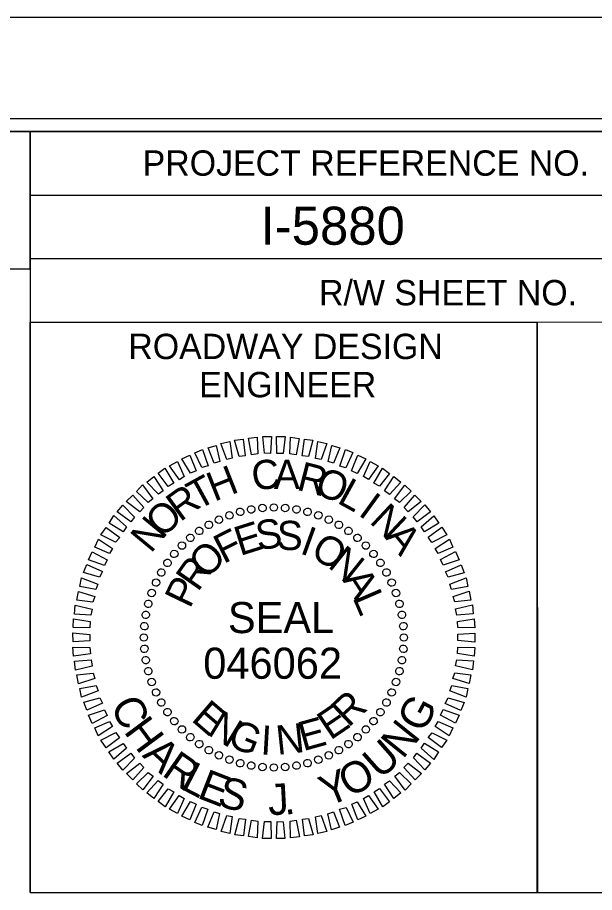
# Model space of a CAD drawing. Extents: x 1640342 to 1730599, y 538663 to 843747.
# Drawn here: x 1730133.49 to 1730156.25, y 539096.41 to 539130.92 of the extents above; entities that cross this region are included whole.
import ezdxf

# ---------------------------------------------------------------- set-up
doc = ezdxf.new("R2010")
doc.units = 0
for name, color, linetype in [('Default', 7, 'Continuous'), ('Old_Level_2', 7, 'Continuous'), ('Prop Dimension Text', 7, 'Continuous'), ('Sheet Data Field CELL', 7, 'Continuous'), ('Sheet Plan CELL', 7, 'Continuous'), ('Sheet Plan Layout CELL', 7, 'Continuous'), ('Sheet Plot Border Inside CELL', 7, 'Continuous'), ('Sheet Plot Border Outside CELL', 7, 'Continuous')]:
    doc.layers.add(name, color=color, linetype=linetype)

msp = doc.modelspace()

# ---------------------------------------------------------------- linework, layer by layer
at = {"layer": 'Old_Level_2'}
for p, q in [((1730142.266, 539111.422), (1730142.266, 539111.422)), ((1730142.715, 539111.512), (1730142.715, 539111.512)), ((1730143.153, 539111.581), (1730143.153, 539111.581)), ((1730143.603, 539111.599), (1730143.603, 539111.599)), ((1730144.053, 539111.576), (1730144.053, 539111.576)), ((1730144.494, 539111.512), (1730144.494, 539111.512)), ((1730144.925, 539111.428), (1730144.925, 539111.428)), ((1730141.433, 539111.121), (1730141.433, 539111.121)), ((1730141.839, 539111.292), (1730141.839, 539111.292)), ((1730145.357, 539111.292), (1730145.357, 539111.292)), ((1730145.769, 539111.115), (1730145.769, 539111.115)), ((1730140.654, 539110.668), (1730140.654, 539110.668)), ((1730141.038, 539110.91), (1730141.038, 539110.91)), ((1730146.171, 539110.918), (1730146.171, 539110.918)), ((1730146.543, 539110.669), (1730146.543, 539110.669)), ((1730140.3, 539110.406), (1730140.3, 539110.406)), ((1730146.906, 539110.399), (1730146.906, 539110.399)), ((1730139.968, 539110.094), (1730139.968, 539110.094)), ((1730147.228, 539110.098), (1730147.228, 539110.098)), ((1730139.667, 539109.771), (1730139.667, 539109.771)), ((1730147.541, 539109.766), (1730147.541, 539109.766)), ((1730139.398, 539109.409), (1730139.398, 539109.409)), ((1730147.803, 539109.412), (1730147.803, 539109.412)), ((1730139.148, 539109.036), (1730139.148, 539109.036)), ((1730148.045, 539109.028), (1730148.045, 539109.028)), ((1730138.951, 539108.634), (1730138.951, 539108.634)), ((1730148.256, 539108.633), (1730148.256, 539108.633)), ((1730138.774, 539108.222), (1730138.774, 539108.222)), ((1730148.427, 539108.227), (1730148.427, 539108.227)), ((1730138.638, 539107.79), (1730138.638, 539107.79)), ((1730148.557, 539107.8), (1730148.557, 539107.8)), ((1730138.554, 539107.359), (1730138.554, 539107.359)), ((1730148.646, 539107.351), (1730148.646, 539107.351)), ((1730138.49, 539106.919), (1730138.49, 539106.919)), ((1730148.715, 539106.913), (1730148.715, 539106.913)), ((1730138.467, 539106.468), (1730138.467, 539106.468)), ((1730143.6, 539106.466), (1730143.6, 539106.466)), ((1730148.733, 539106.463), (1730148.733, 539106.463)), ((1730138.485, 539106.019), (1730138.485, 539106.019)), ((1730148.711, 539106.013), (1730148.711, 539106.013)), ((1730138.554, 539105.58), (1730138.554, 539105.58)), ((1730148.647, 539105.572), (1730148.647, 539105.572)), ((1730138.644, 539105.132), (1730138.644, 539105.132)), ((1730148.562, 539105.141), (1730148.562, 539105.141)), ((1730138.774, 539104.705), (1730138.774, 539104.705)), ((1730148.427, 539104.709), (1730148.427, 539104.709)), ((1730138.945, 539104.299), (1730138.945, 539104.299)), ((1730148.25, 539104.297), (1730148.25, 539104.297)), ((1730139.156, 539103.903), (1730139.156, 539103.903)), ((1730148.052, 539103.895), (1730148.052, 539103.895)), ((1730139.398, 539103.519), (1730139.398, 539103.519)), ((1730147.803, 539103.523), (1730147.803, 539103.523)), ((1730139.66, 539103.166), (1730139.66, 539103.166)), ((1730147.533, 539103.16), (1730147.533, 539103.16)), ((1730139.972, 539102.834), (1730139.972, 539102.834)), ((1730147.232, 539102.838), (1730147.232, 539102.838)), ((1730140.295, 539102.533), (1730140.295, 539102.533)), ((1730146.9, 539102.525), (1730146.9, 539102.525)), ((1730140.657, 539102.263), (1730140.657, 539102.263)), ((1730141.03, 539102.014), (1730141.03, 539102.014)), ((1730146.163, 539102.022), (1730146.163, 539102.022)), ((1730146.547, 539102.264), (1730146.547, 539102.264)), ((1730141.432, 539101.816), (1730141.432, 539101.816)), ((1730141.844, 539101.64), (1730141.844, 539101.64)), ((1730145.362, 539101.64), (1730145.362, 539101.64)), ((1730145.768, 539101.81), (1730145.768, 539101.81)), ((1730142.276, 539101.504), (1730142.276, 539101.504)), ((1730142.707, 539101.419), (1730142.707, 539101.419)), ((1730143.148, 539101.355), (1730143.148, 539101.355)), ((1730143.598, 539101.333), (1730143.598, 539101.333)), ((1730144.048, 539101.351), (1730144.048, 539101.351)), ((1730144.486, 539101.42), (1730144.486, 539101.42)), ((1730144.934, 539101.509), (1730144.934, 539101.509))]:
    msp.add_line(p, q, dxfattribs=at)
for points in [[(1730141.74, 539113.479), (1730141.514, 539114.119), (1730141.86, 539114.196), (1730141.953, 539113.533)], [(1730142.228, 539113.6), (1730142.053, 539114.251), (1730142.39, 539114.287), (1730142.473, 539113.634)], [(1730142.718, 539113.669), (1730142.594, 539114.322), (1730142.941, 539114.369), (1730142.963, 539113.704)], [(1730143.228, 539113.729), (1730143.165, 539114.393), (1730143.503, 539114.389), (1730143.474, 539113.724)], [(1730143.719, 539113.728), (1730143.707, 539114.392), (1730144.045, 539114.388), (1730143.965, 539113.722)], [(1730144.231, 539113.706), (1730144.26, 539114.371), (1730144.598, 539114.316), (1730144.477, 539113.669)], [(1730144.723, 539113.633), (1730144.803, 539114.289), (1730145.142, 539114.243), (1730144.969, 539113.606)], [(1730145.246, 539113.53), (1730145.337, 539114.196), (1730145.686, 539114.12), (1730145.462, 539113.482)], [(1730140.753, 539113.165), (1730140.477, 539113.753), (1730140.782, 539113.881), (1730141.008, 539113.231)], [(1730141.251, 539113.337), (1730141.005, 539113.946), (1730141.321, 539114.044), (1730141.465, 539113.412)], [(1730145.739, 539113.405), (1730145.881, 539114.042), (1730146.2, 539113.945), (1730145.955, 539113.337)], [(1730146.202, 539113.229), (1730146.426, 539113.877), (1730146.714, 539113.76), (1730146.439, 539113.162)], [(1730139.872, 539112.689), (1730139.484, 539113.235), (1730139.798, 539113.404), (1730140.064, 539112.815)], [(1730140.307, 539112.942), (1730139.97, 539113.509), (1730140.285, 539113.658), (1730140.531, 539113.038)], [(1730146.666, 539113.043), (1730146.911, 539113.651), (1730147.23, 539113.513), (1730146.892, 539112.934)], [(1730147.14, 539112.816), (1730147.406, 539113.404), (1730147.715, 539113.235), (1730147.336, 539112.697)], [(1730139.427, 539112.426), (1730139.039, 539112.941), (1730139.302, 539113.139), (1730139.649, 539112.552)], [(1730147.543, 539112.547), (1730147.891, 539113.146), (1730148.16, 539112.936), (1730147.77, 539112.428)], [(1730139.044, 539112.112), (1730138.595, 539112.595), (1730138.868, 539112.815), (1730139.235, 539112.249)], [(1730147.968, 539112.248), (1730148.336, 539112.817), (1730148.606, 539112.596), (1730148.165, 539112.108)], [(1730138.64, 539111.788), (1730138.183, 539112.23), (1730138.424, 539112.48), (1730138.832, 539111.935)], [(1730148.362, 539111.938), (1730148.772, 539112.476), (1730149.021, 539112.235), (1730148.559, 539111.788)], [(1730138.309, 539111.425), (1730137.78, 539111.835), (1730138.032, 539112.074), (1730138.47, 539111.591)], [(1730148.736, 539111.586), (1730149.167, 539112.074), (1730149.417, 539111.833), (1730148.892, 539111.425)], [(1730137.958, 539111.03), (1730137.42, 539111.419), (1730137.64, 539111.689), (1730138.098, 539111.217)], [(1730149.1, 539111.225), (1730149.562, 539111.693), (1730149.782, 539111.42), (1730149.247, 539111.023)], [(1730137.658, 539110.636), (1730137.1, 539110.974), (1730137.289, 539111.274), (1730137.788, 539110.833)], [(1730149.414, 539110.831), (1730149.907, 539111.269), (1730150.107, 539110.976), (1730149.54, 539110.639)], [(1730137.359, 539110.222), (1730136.781, 539110.519), (1730136.98, 539110.808), (1730137.519, 539110.409)], [(1730149.687, 539110.417), (1730150.222, 539110.815), (1730150.422, 539110.511), (1730149.834, 539110.215)], [(1730137.121, 539109.778), (1730136.534, 539110.024), (1730136.682, 539110.343), (1730137.24, 539109.975)], [(1730149.961, 539109.972), (1730150.527, 539110.339), (1730150.665, 539110.025), (1730150.087, 539109.78)], [(1730136.925, 539109.304), (1730136.287, 539109.528), (1730136.435, 539109.848), (1730137.023, 539109.531)], [(1730150.173, 539109.536), (1730150.77, 539109.853), (1730150.909, 539109.528), (1730150.279, 539109.313)], [(1730136.728, 539108.851), (1730136.091, 539109.024), (1730136.219, 539109.343), (1730136.837, 539109.068)], [(1730150.365, 539109.058), (1730150.984, 539109.335), (1730151.102, 539109.02), (1730150.471, 539108.846)], [(1730136.583, 539108.358), (1730135.947, 539108.48), (1730136.013, 539108.818), (1730136.662, 539108.574)], [(1730150.537, 539108.571), (1730151.187, 539108.817), (1730151.255, 539108.481), (1730150.613, 539108.357)], [(1730136.459, 539107.865), (1730135.824, 539107.935), (1730135.889, 539108.284), (1730136.537, 539108.081)], [(1730150.668, 539108.082), (1730151.309, 539108.288), (1730151.376, 539107.941), (1730150.734, 539107.868)], [(1730136.386, 539107.342), (1730135.731, 539107.392), (1730135.766, 539107.74), (1730136.433, 539107.588)], [(1730150.769, 539107.593), (1730151.431, 539107.748), (1730151.468, 539107.401), (1730150.814, 539107.348)], [(1730136.344, 539106.85), (1730135.679, 539106.859), (1730135.694, 539107.197), (1730136.36, 539107.096)], [(1730150.839, 539107.103), (1730151.502, 539107.197), (1730151.528, 539106.85), (1730150.864, 539106.858)], [(1730136.343, 539106.339), (1730135.679, 539106.297), (1730135.673, 539106.644), (1730136.338, 539106.584)], [(1730150.858, 539106.592), (1730151.522, 539106.635), (1730151.528, 539106.287), (1730150.862, 539106.347)], [(1730136.362, 539105.828), (1730135.699, 539105.735), (1730135.672, 539106.082), (1730136.337, 539106.073)], [(1730150.857, 539106.081), (1730151.522, 539106.072), (1730151.507, 539105.735), (1730150.841, 539105.836)], [(1730136.432, 539105.339), (1730135.77, 539105.184), (1730135.733, 539105.531), (1730136.387, 539105.583)], [(1730150.814, 539105.59), (1730151.47, 539105.54), (1730151.435, 539105.191), (1730150.767, 539105.343)], [(1730136.532, 539104.85), (1730135.892, 539104.644), (1730135.824, 539104.991), (1730136.467, 539105.063)], [(1730150.742, 539105.067), (1730151.377, 539104.996), (1730151.311, 539104.647), (1730150.664, 539104.851)], [(1730136.663, 539104.361), (1730136.013, 539104.114), (1730135.946, 539104.451), (1730136.588, 539104.574)], [(1730150.617, 539104.574), (1730151.253, 539104.452), (1730151.188, 539104.114), (1730150.539, 539104.358)], [(1730136.836, 539103.873), (1730136.217, 539103.597), (1730136.099, 539103.911), (1730136.73, 539104.086)], [(1730150.472, 539104.081), (1730151.109, 539103.908), (1730150.982, 539103.588), (1730150.364, 539103.864)], [(1730137.028, 539103.396), (1730136.43, 539103.079), (1730136.292, 539103.404), (1730136.922, 539103.619)], [(1730150.276, 539103.627), (1730150.914, 539103.403), (1730150.766, 539103.084), (1730150.178, 539103.401)], [(1730137.24, 539102.96), (1730136.674, 539102.592), (1730136.535, 539102.907), (1730137.114, 539103.152)], [(1730150.08, 539103.153), (1730150.667, 539102.908), (1730150.519, 539102.588), (1730149.96, 539102.957)], [(1730137.514, 539102.515), (1730136.979, 539102.117), (1730136.779, 539102.42), (1730137.367, 539102.717)], [(1730149.842, 539102.71), (1730150.42, 539102.413), (1730150.22, 539102.123), (1730149.682, 539102.523)], [(1730137.787, 539102.1), (1730137.293, 539101.662), (1730137.094, 539101.955), (1730137.661, 539102.292)], [(1730149.542, 539102.295), (1730150.101, 539101.957), (1730149.911, 539101.658), (1730149.413, 539102.099)], [(1730138.1, 539101.707), (1730137.638, 539101.239), (1730137.419, 539101.511), (1730137.954, 539101.909)], [(1730149.243, 539101.902), (1730149.781, 539101.512), (1730149.561, 539101.242), (1730149.103, 539101.715)], [(1730138.465, 539101.345), (1730138.033, 539100.857), (1730137.784, 539101.098), (1730138.308, 539101.506)], [(1730148.892, 539101.507), (1730149.42, 539101.097), (1730149.169, 539100.857), (1730148.731, 539101.34)], [(1730138.839, 539100.994), (1730138.429, 539100.455), (1730138.179, 539100.696), (1730138.642, 539101.144)], [(1730148.56, 539101.143), (1730149.018, 539100.701), (1730148.777, 539100.452), (1730148.369, 539100.997)], [(1730139.233, 539100.684), (1730138.864, 539100.115), (1730138.595, 539100.335), (1730139.036, 539100.824)], [(1730148.157, 539100.819), (1730148.605, 539100.336), (1730148.333, 539100.117), (1730147.965, 539100.683)], [(1730139.657, 539100.385), (1730139.31, 539099.785), (1730139.04, 539099.995), (1730139.43, 539100.503)], [(1730147.774, 539100.506), (1730148.161, 539099.991), (1730147.899, 539099.792), (1730147.551, 539100.379)], [(1730140.061, 539100.115), (1730139.795, 539099.528), (1730139.485, 539099.696), (1730139.864, 539100.235)], [(1730140.535, 539099.889), (1730140.29, 539099.281), (1730139.971, 539099.419), (1730140.308, 539099.997)], [(1730146.893, 539099.989), (1730147.231, 539099.423), (1730146.916, 539099.274), (1730146.67, 539099.893)], [(1730147.329, 539100.242), (1730147.717, 539099.697), (1730147.403, 539099.528), (1730147.137, 539100.116)], [(1730140.998, 539099.702), (1730140.775, 539099.054), (1730140.486, 539099.172), (1730140.762, 539099.77)], [(1730141.462, 539099.526), (1730141.319, 539098.89), (1730141.001, 539098.987), (1730141.246, 539099.594)], [(1730145.949, 539099.595), (1730146.195, 539098.985), (1730145.88, 539098.888), (1730145.736, 539099.519)], [(1730146.447, 539099.767), (1730146.724, 539099.179), (1730146.419, 539099.051), (1730146.193, 539099.701)], [(1730141.955, 539099.402), (1730141.864, 539098.736), (1730141.515, 539098.812), (1730141.739, 539099.449)], [(1730142.478, 539099.299), (1730142.397, 539098.643), (1730142.059, 539098.688), (1730142.232, 539099.325)], [(1730142.97, 539099.226), (1730142.941, 539098.56), (1730142.602, 539098.616), (1730142.724, 539099.262)], [(1730144.483, 539099.262), (1730144.607, 539098.61), (1730144.26, 539098.563), (1730144.238, 539099.227)], [(1730144.972, 539099.332), (1730145.147, 539098.681), (1730144.811, 539098.644), (1730144.728, 539099.297)], [(1730145.461, 539099.453), (1730145.687, 539098.813), (1730145.341, 539098.735), (1730145.247, 539099.398)], [(1730143.482, 539099.204), (1730143.493, 539098.539), (1730143.156, 539098.544), (1730143.236, 539099.21)], [(1730143.973, 539099.202), (1730144.035, 539098.539), (1730143.698, 539098.543), (1730143.727, 539099.208)]]:
    msp.add_lwpolyline(points, close=True, dxfattribs=at)
for centre, major_axis in [((1730142.71, 539111.516), (-0.026, 0.145)), ((1730143.153, 539111.574), (-0.013, 0.147)), ((1730143.6, 539111.594), (0, 0.147)), ((1730144.047, 539111.574), (0.013, 0.147)), ((1730144.491, 539111.516), (0.026, 0.145)), ((1730141.846, 539111.285), (-0.05, 0.138)), ((1730142.273, 539111.419), (-0.038, 0.142)), ((1730144.928, 539111.419), (0.038, 0.142)), ((1730145.354, 539111.285), (0.05, 0.138)), ((1730141.036, 539110.907), (-0.074, 0.127)), ((1730141.433, 539111.114), (-0.062, 0.133)), ((1730145.768, 539111.114), (0.062, 0.133)), ((1730146.164, 539110.907), (0.074, 0.127)), ((1730140.659, 539110.667), (-0.084, 0.121)), ((1730146.542, 539110.667), (0.084, 0.121)), ((1730140.304, 539110.394), (-0.095, 0.113)), ((1730146.897, 539110.394), (0.095, 0.113)), ((1730139.672, 539109.762), (-0.113, 0.095)), ((1730139.974, 539110.092), (-0.104, 0.104)), ((1730147.227, 539110.092), (0.104, 0.104)), ((1730147.529, 539109.762), (0.113, 0.095)), ((1730139.4, 539109.407), (-0.121, 0.084)), ((1730147.801, 539109.407), (0.121, 0.084)), ((1730139.159, 539109.03), (-0.127, 0.074)), ((1730148.042, 539109.03), (0.127, 0.074)), ((1730138.953, 539108.633), (-0.133, 0.062)), ((1730148.248, 539108.633), (0.133, 0.062)), ((1730138.781, 539108.22), (-0.138, 0.05)), ((1730148.419, 539108.22), (0.138, 0.05)), ((1730138.647, 539107.793), (-0.142, 0.038)), ((1730148.554, 539107.793), (0.142, 0.038)), ((1730138.55, 539107.356), (-0.145, 0.026)), ((1730148.651, 539107.356), (0.145, 0.026)), ((1730138.492, 539106.913), (-0.147, 0.013)), ((1730148.709, 539106.913), (0.147, 0.013)), ((1730138.472, 539106.466), (-0.147, 0)), ((1730148.729, 539106.466), (0.147, 0)), ((1730138.492, 539106.019), (-0.147, -0.013)), ((1730148.709, 539106.019), (0.147, -0.013)), ((1730138.55, 539105.575), (-0.145, -0.026)), ((1730148.651, 539105.575), (0.145, -0.026)), ((1730138.647, 539105.139), (-0.142, -0.038)), ((1730148.554, 539105.139), (0.142, -0.038)), ((1730138.781, 539104.712), (-0.138, -0.05)), ((1730148.419, 539104.712), (0.138, -0.05)), ((1730138.953, 539104.299), (-0.133, -0.062)), ((1730148.248, 539104.299), (0.133, -0.062)), ((1730139.159, 539103.902), (-0.127, -0.074)), ((1730148.042, 539103.902), (0.127, -0.074)), ((1730139.4, 539103.524), (-0.121, -0.084)), ((1730147.801, 539103.524), (0.121, -0.084)), ((1730139.672, 539103.169), (-0.113, -0.095)), ((1730147.529, 539103.169), (0.113, -0.095)), ((1730139.974, 539102.84), (-0.104, -0.104)), ((1730140.304, 539102.537), (-0.095, -0.113)), ((1730146.897, 539102.537), (0.095, -0.113)), ((1730147.227, 539102.84), (0.104, -0.104)), ((1730140.659, 539102.265), (-0.084, -0.121)), ((1730146.542, 539102.265), (0.084, -0.121)), ((1730141.036, 539102.025), (-0.074, -0.127)), ((1730141.433, 539101.818), (-0.062, -0.133)), ((1730145.768, 539101.818), (0.062, -0.133)), ((1730146.164, 539102.025), (0.074, -0.127)), ((1730141.846, 539101.647), (-0.05, -0.138)), ((1730142.273, 539101.512), (-0.038, -0.142)), ((1730144.928, 539101.512), (0.038, -0.142)), ((1730145.354, 539101.647), (0.05, -0.138)), ((1730142.71, 539101.416), (-0.026, -0.145)), ((1730143.153, 539101.357), (-0.013, -0.147)), ((1730143.6, 539101.338), (0, -0.147)), ((1730144.047, 539101.357), (0.013, -0.147)), ((1730144.491, 539101.416), (0.026, -0.145))]:
    msp.add_ellipse(centre, major_axis=major_axis, ratio=0.999708, dxfattribs=at)
at = {"layer": 'Prop Dimension Text'}
msp.add_lwpolyline([(1730104.001, 539121.01), (1730133.983, 539121.01), (1730133.983, 539126.42), (1730104.001, 539126.42)], close=True, dxfattribs=at)
at = {"layer": 'Sheet Plan CELL'}
for p, q in [((1730133.98, 539123.91), (1730173.99, 539123.908)), ((1730133.983, 539121.403), (1730173.99, 539121.408)), ((1730133.983, 539121.403), (1730173.99, 539121.408)), ((1730133.983, 539121.403), (1730133.983, 539118.905)), ((1730153.993, 539118.905), (1730153.995, 539096.413))]:
    msp.add_line(p, q, dxfattribs=at)
for points in [[(1729873.99, 538916.418), (1729873.985, 539126.413), (1730133.983, 539126.42), (1730133.985, 539096.408), (1730173.993, 539096.405), (1730173.993, 538916.418)], [(1730173.998, 539126.418), (1729873.99, 539126.418), (1729873.99, 538916.418), (1730173.993, 538916.418)], [(1730133.983, 539126.42), (1730173.998, 539126.418), (1730173.99, 539121.408), (1730133.983, 539121.403)], [(1730133.983, 539118.905), (1730153.993, 539118.905), (1730153.993, 539096.403), (1730133.985, 539096.408)], [(1730153.993, 539118.905), (1730173.99, 539118.908), (1730173.993, 539096.405), (1730153.993, 539096.403)]]:
    msp.add_lwpolyline(points, close=True, dxfattribs=at)
at = {"layer": 'Sheet Plan Layout CELL'}
msp.add_lwpolyline([(1730126.14, 539084.12), (1730173.995, 539084.12), (1730174, 539126.418), (1730126.14, 539126.418)], close=True, dxfattribs=at)
at = {"layer": 'Sheet Plot Border Inside CELL'}
msp.add_lwpolyline([(1729843.293, 538915.915), (1730176.49, 538915.918), (1730176.493, 539126.915), (1729843.293, 539126.915)], close=True, dxfattribs=at)
at = {"layer": 'Sheet Plot Border Outside CELL'}
msp.add_lwpolyline([(1729840.693, 538911.915), (1730177.393, 538911.915), (1730177.393, 539130.915), (1729840.693, 539130.915)], close=True, dxfattribs=at)

# ---------------------------------------------------------------- texts
at = {"layer": 'Default'}
for s, rotation, p in [('C', 297.1999, (1730137.125, 539103.781)), ('G', 61.7998, (1730149.488, 539102.654)), ('H', 306.6436, (1730137.652, 539102.755)), ('N', 51.2288, (1730148.689, 539101.638)), ('A', 316.4834, (1730138.374, 539101.792)), ('U', 41.4347, (1730147.794, 539100.843)), ('R', 325.1961, (1730139.141, 539101.054)), ('L', 332.5683, (1730139.872, 539100.527)), ('Y', 22.2426, (1730145.714, 539099.778)), ('O', 30.0413, (1730146.602, 539100.126)), ('E', 338.7525, (1730140.534, 539100.159)), ('S', 345.7591, (1730141.325, 539099.832)), ('J', 3.0321, (1730143.397, 539099.455)), ('.', 8.214, (1730144.031, 539099.465))]:
    msp.add_text(s, height=1.226, rotation=rotation, dxfattribs=at).set_placement(p)
at = {"layer": 'Old_Level_2'}
for s, rotation, p in [('C', 7.2199, (1730142.794, 539112.249)), ('A', 0.0203, (1730143.6, 539112.325)), ('R', 345.6211, (1730144.46, 539112.299)), ('H', 21.6195, (1730141.247, 539111.813)), ('O', 338.4212, (1730145.147, 539112.158)), ('T', 28.8198, (1730140.589, 539111.465)), ('L', 331.2209, (1730146.053, 539111.795)), ('R', 36.0205, (1730139.901, 539111.003)), ('I', 324.0201, (1730146.89, 539111.319)), ('O', 43.2217, (1730139.207, 539110.357)), ('N', 316.8189, (1730147.335, 539111.01)), ('N', 50.4235, (1730138.747, 539109.755)), ('E', 17.6111, (1730142.266, 539109.674)), ('S', 8.2556, (1730142.968, 539109.901)), ('S', 358.9004, (1730143.704, 539109.924)), ('F', 26.967, (1730141.617, 539109.356)), ('I', 340.1896, (1730144.585, 539109.796)), ('A', 309.6172, (1730147.949, 539110.417)), ('O', 330.8335, (1730144.997, 539109.66)), ('O', 45.6812, (1730140.953, 539108.741)), ('N', 321.4766, (1730145.689, 539109.263)), ('R', 55.0397, (1730140.604, 539108.234)), ('A', 302.7603, (1730146.281, 539108.742)), ('P', 64.3989, (1730140.288, 539107.574)), ('L', 293.4009, (1730146.692, 539108.043)), ('R', 43.4814, (1730146.546, 539102.887)), ('E', 319.2769, (1730140.303, 539103.208)), ('E', 34.1241, (1730145.829, 539102.394)), ('N', 328.634, (1730140.926, 539102.666)), ('G', 337.9902, (1730141.711, 539102.22)), ('N', 6.0564, (1730143.743, 539101.836)), ('E', 15.4118, (1730144.752, 539101.977)), ('I', 356.7012, (1730143.057, 539101.855))]:
    msp.add_text(s, height=1.153, rotation=rotation, dxfattribs=at).set_placement(p)
for s, height, p in [('SEAL', 1.2265, (1730141.787, 539106.639)), ('046062', 1.2268, (1730140.815, 539104.839))]:
    msp.add_text(s, height=height, dxfattribs=at).set_placement(p)
at = {"layer": 'Sheet Data Field CELL'}
msp.add_text('I-5880', height=1.5, rotation=0, dxfattribs=at).set_placement((1730143.079, 539121.955))
at = {"layer": 'Sheet Plan CELL'}
for s, height, p in [('PROJECT REFERENCE NO.', 1.00002, (1730138.423, 539124.675)), ('R/W SHEET NO.', 1.00002, (1730145.383, 539119.565)), ('ROADWAY DESIGN', 1.00002, (1730137.858, 539117.445)), ('ENGINEER', 1, (1730140.655, 539115.938))]:
    msp.add_text(s, height=height, rotation=0, dxfattribs=at).set_placement(p)

doc.saveas('drawing.dxf')
